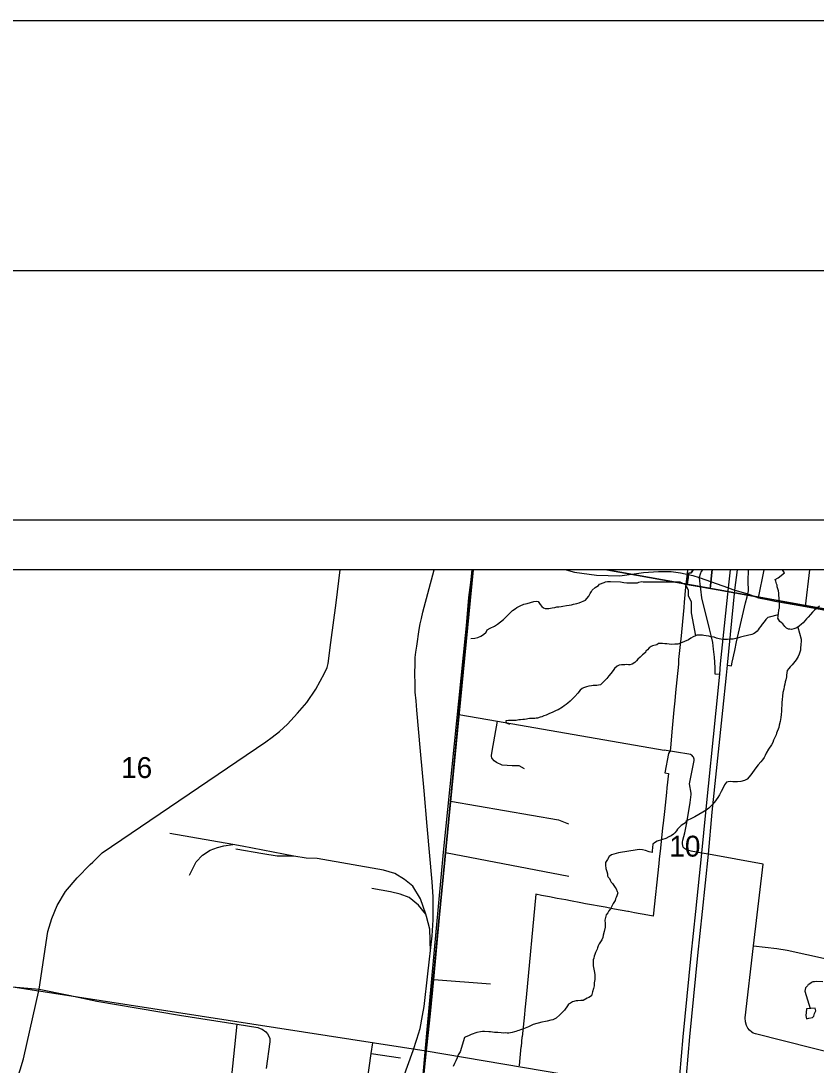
# Model space of a CAD drawing. Extents: x 0 to 34, y -3.9 to 26.2.
# Drawn here: x 6.412 to 8.005, y 19.908 to 22 of the extents above; entities that cross this region are included whole.
import ezdxf

# ---------------------------------------------------------------- set-up
doc = ezdxf.new("R2010")
doc.units = 0
for name, color, linetype in [('GM_X_City_Street', 7, 'Continuous'), ('GM_X_County_Road', 7, 'Continuous'), ('GM_X_Interchange_Ramps', 7, 'Continuous'), ('GM_X_Interstate_Route', 7, 'Continuous'), ('GM_X_Minor_River', 7, 'Continuous'), ('GM_X_Rail_Line', 7, 'Continuous'), ('GM_X_Section', 7, 'Continuous'), ('GM_X_Section_Text', 7, 'Continuous'), ('GM_X_State_Shield', 7, 'Continuous'), ('SH_Border', 7, 'Continuous'), ('SH_Cut_Line', 7, 'Continuous'), ('SH_Data', 7, 'Continuous')]:
    doc.layers.add(name, color=color, linetype=linetype)

msp = doc.modelspace()

# ---------------------------------------------------------------- linework, layer by layer
at = {"layer": 'GM_X_City_Street'}
for p, q in [((7.8891, 20.8439), (7.9002, 20.9)), ((7.9835, 20.8269), (7.9917, 20.9)), ((7.2626, 20.3339), (7.5094, 20.286)), ((7.2392, 20.0793), (7.3526, 20.0709)), ((6.8308, 19.8528), (6.8451, 19.9898)), ((7.1137, 19.9307), (7.1725, 19.9225))]:
    msp.add_line(p, q, dxfattribs=at)
for points in [[(7.289, 20.6105), (7.3664, 20.597), (7.7001, 20.5391)], [(7.4205, 20.5016), (7.41, 20.5071), (7.3959, 20.5074), (7.3759, 20.509), (7.3642, 20.5142), (7.36, 20.5175), (7.3564, 20.5212), (7.3549, 20.5233), (7.3543, 20.5262), (7.3543, 20.5282), (7.3556, 20.5368), (7.3664, 20.597)], [(8.1685, 19.8985), (7.8829, 19.9702), (7.8784, 19.9719), (7.8756, 19.9736), (7.871, 19.9781), (7.8675, 19.982), (7.8651, 19.987), (7.8629, 19.9942), (7.8624, 20.0022), (7.8793, 20.1469), (7.8984, 20.3101), (7.7888, 20.3303), (7.7757, 20.3323), (7.7545, 20.3364), (7.7449, 20.3392), (7.7412, 20.3415), (7.7384, 20.3445), (7.7374, 20.3477), (7.7367, 20.3511), (7.7367, 20.3545), (7.7376, 20.3584), (7.7416, 20.3731), (7.7455, 20.3932), (7.752, 20.4342), (7.754, 20.4497), (7.754, 20.4524), (7.751, 20.4711), (7.7605, 20.5183), (7.7606, 20.5194), (7.7604, 20.5206), (7.7599, 20.5226), (7.7589, 20.5245), (7.7578, 20.5264), (7.7563, 20.5279), (7.755, 20.5289), (7.7533, 20.5298), (7.7496, 20.5311), (7.7001, 20.5391)], [(7.2724, 20.4369), (7.4884, 20.3989), (7.5087, 20.3913)], [(7.8793, 20.1469), (7.9261, 20.1415), (7.9469, 20.138), (8.0251, 20.121), (8.187, 20.0848)], [(7.0598, 19.6739), (7.0846, 19.7416), (7.0857, 19.7471), (7.0871, 19.7545), (7.0914, 19.7791), (7.1047, 19.8692), (7.1137, 19.9307), (7.1169, 19.9525)]]:
    msp.add_lwpolyline(points, dxfattribs=at)
at = {"layer": 'GM_X_County_Road'}
for points in [[(7.0326, 20.7544), (7.0431, 20.8337), (7.0513, 20.9)], [(7.19, 19.616), (7.1965, 19.6759), (7.205, 19.7546), (7.2132, 19.8305), (7.2174, 19.8691), (7.2205, 19.8992), (7.232, 20.0102), (7.2392, 20.0793), (7.2626, 20.3339), (7.2648, 20.3579), (7.2724, 20.4369), (7.289, 20.6105), (7.2945, 20.6675), (7.3089, 20.8445), (7.3161, 20.9)], [(7.5041, 20.9), (7.5206, 20.8956), (7.565, 20.8893), (7.6112, 20.8881), (7.6588, 20.8945), (7.6891, 20.8966), (7.7133, 20.8969)], [(7.7133, 20.8969), (7.7143, 20.8969), (7.7327, 20.8941), (7.7579, 20.8889), (7.7704, 20.8845), (7.8288, 20.8641), (7.8381, 20.861)], [(7.8381, 20.861), (7.8418, 20.8597), (7.8678, 20.8517), (7.8891, 20.8439), (7.9098, 20.84)], [(7.9098, 20.84), (7.9222, 20.8376), (7.9452, 20.8334), (7.9835, 20.8269), (8.0488, 20.8145)], [(6.9025, 20.5558), (6.9155, 20.5646), (6.9302, 20.5765), (6.946, 20.5906), (6.9658, 20.6129), (6.9845, 20.6346), (7.0029, 20.6612), (7.0203, 20.6928), (7.0253, 20.7042), (7.0271, 20.7123), (7.0326, 20.7544)], [(6.5558, 20.3144), (6.5745, 20.333), (6.9025, 20.5558)], [(6.2305, 19.6109), (6.2359, 19.6363), (6.2456, 19.6657), (6.2619, 19.7003), (6.2842, 19.7336), (6.3083, 19.7593), (6.3505, 19.8029), (6.3708, 19.8294), (6.3931, 19.8631), (6.3999, 19.8751), (6.4077, 19.8905), (6.4106, 19.898), (6.417, 19.92), (6.4489, 20.0597), (6.4662, 20.1757), (6.4739, 20.2018), (6.4847, 20.2277), (6.5016, 20.2559), (6.5249, 20.2831), (6.5509, 20.3095), (6.5558, 20.3144)], [(6.3797, 20.0659), (6.4489, 20.0597), (6.5081, 20.0476)], [(6.5081, 20.0476), (6.5644, 20.0361), (6.7293, 20.0075), (6.8451, 19.9898)], [(6.8451, 19.9898), (6.8863, 19.9829), (6.8913, 19.9814), (6.8951, 19.9798), (6.9022, 19.9745), (6.9061, 19.9705), (6.9106, 19.9615), (6.9105, 19.9543), (6.9035, 19.9008)]]:
    msp.add_lwpolyline(points, dxfattribs=at)
at = {"layer": 'GM_X_Interchange_Ramps'}
for points in [[(8.9, 20.9), (7.7963, 20.9), (7.7958, 20.8952), (7.7932, 20.8682), (7.7927, 20.8627), (7.7701, 20.8667), (7.754, 20.8696), (7.7466, 20.8709), (7.7473, 20.8764), (7.7476, 20.8796), (7.749, 20.8913), (7.7492, 20.8934), (7.754, 20.894), (7.7581, 20.9), (7.747, 20.9), (7.7462, 20.893), (7.7462, 20.8929), (7.7449, 20.8812), (7.7444, 20.8769), (7.7437, 20.8714), (7.7432, 20.8655), (7.7404, 20.8354), (7.7394, 20.8249), (7.7334, 20.7614), (7.7329, 20.7564), (7.7291, 20.7206), (7.7287, 20.7111), (7.7256, 20.6796), (7.7231, 20.6543), (7.7215, 20.6374), (7.7197, 20.6194), (7.7161, 20.5828), (7.7129, 20.5432), (7.7124, 20.5374), (7.709, 20.5323), (7.7015, 20.4932), (7.7087, 20.4918), (7.7057, 20.4631), (7.7047, 20.4538), (7.7007, 20.4159), (7.6982, 20.3923), (7.6972, 20.3829), (7.6928, 20.3423), (7.6905, 20.3205), (7.6896, 20.3117), (7.6783, 20.2059), (7.6674, 20.208), (7.641, 20.213), (7.629, 20.2153), (7.6274, 20.2156), (7.6006, 20.2205), (7.5818, 20.2239), (7.5425, 20.2312), (7.5332, 20.233), (7.5125, 20.2369), (7.503, 20.2387), (7.4863, 20.2419), (7.4703, 20.2449), (7.4543, 20.2479), (7.443, 20.25), (7.4237, 20.0431), (7.4214, 20.0186), (7.4205, 20.0092), (7.4162, 19.9645), (7.4155, 19.9642), (7.4136, 19.9447), (7.4135, 19.9442), (7.4106, 19.9147), (7.4098, 19.9061)], [(7.777, 20.9), (7.7746, 20.8965), (7.7725, 20.8914), (7.7704, 20.8845)], [(7.7704, 20.8845), (7.7708, 20.8773), (7.7727, 20.8614), (7.7748, 20.8442), (7.7904, 20.7817), (7.7937, 20.7686), (7.7968, 20.7545), (7.7986, 20.7409), (7.8005, 20.7253), (7.8017, 20.7047), (7.8017, 20.6919), (7.8115, 20.6908)], [(7.8678, 20.8517), (7.869, 20.858), (7.8682, 20.8773), (7.869, 20.9)], [(7.8416, 20.7382), (7.8453, 20.7556), (7.8634, 20.8338), (7.8668, 20.8463), (7.8678, 20.8517)], [(7.8274, 20.7089), (7.8352, 20.708), (7.8367, 20.7153), (7.8416, 20.7382)]]:
    msp.add_lwpolyline(points, dxfattribs=at)
msp.add_lwpolyline([(7.7963, 20.9), (7.7581, 20.9), (7.754, 20.894), (7.7492, 20.8934), (7.749, 20.8913), (7.7476, 20.8796), (7.7473, 20.8764), (7.7466, 20.8709), (7.754, 20.8696), (7.7701, 20.8667), (7.7927, 20.8627), (7.7932, 20.8682), (7.7958, 20.8952)], close=True, dxfattribs=at)
at = {"layer": 'GM_X_Interstate_Route'}
for points in [[(8.9, 20.9), (3.1989, 20.9)], [(7.7314, 19.2555), (7.7327, 19.2893), (7.7318, 19.3378), (7.731, 19.3812), (7.7304, 19.4407), (7.7292, 19.4983), (7.7266, 19.6567), (7.7259, 19.7271), (7.7266, 19.7817), (7.7283, 19.8306), (7.7314, 19.8867), (7.7382, 19.9644), (7.7546, 20.1271), (7.7636, 20.2157), (7.7757, 20.3323), (7.7834, 20.4142), (7.8044, 20.6184), (7.8115, 20.6908), (7.8134, 20.7118), (7.8288, 20.8641), (7.8333, 20.9)], [(7.7421, 19.2233), (7.7429, 19.2303), (7.7447, 19.2555), (7.746, 19.2893), (7.7451, 19.3378), (7.7443, 19.3812), (7.7438, 19.4384), (7.7425, 19.4983), (7.7399, 19.6567), (7.7392, 19.7271), (7.7399, 19.7817), (7.7416, 19.8306), (7.7447, 19.8868), (7.7515, 19.9644), (7.768, 20.1272), (7.7769, 20.2158), (7.7888, 20.3303), (7.7967, 20.4143), (7.8177, 20.6185), (7.8248, 20.6893), (7.8274, 20.7089), (7.8418, 20.8597), (7.8468, 20.9)]]:
    msp.add_lwpolyline(points, dxfattribs=at)
at = {"layer": 'GM_X_Minor_River'}
for p, q in [((7.941, 20.8941), (7.9372, 20.9)), ((8.0028, 20.0218), (7.9852, 20.0203))]:
    msp.add_line(p, q, dxfattribs=at)
for points in [[(8.0111, 20.8273), (8.0016, 20.8193), (7.9976, 20.8153), (7.9932, 20.8105), (7.9887, 20.8053), (7.9852, 20.8017), (7.9823, 20.798), (7.9787, 20.794), (7.9755, 20.791), (7.9708, 20.7874), (7.9657, 20.7838), (7.9599, 20.7818), (7.9556, 20.7808), (7.9518, 20.781), (7.9491, 20.7814), (7.9454, 20.7835), (7.9417, 20.7863), (7.9377, 20.7918), (7.9348, 20.7949), (7.9322, 20.7969), (7.93, 20.7997), (7.9282, 20.8032), (7.9287, 20.8058), (7.9291, 20.8142), (7.93, 20.818), (7.9301, 20.8206), (7.931, 20.8236), (7.9314, 20.8335), (7.9311, 20.8362), (7.9307, 20.8434), (7.9298, 20.8492), (7.9296, 20.8534), (7.929, 20.8583), (7.928, 20.8618), (7.9267, 20.8658), (7.9264, 20.8691), (7.9253, 20.8718), (7.9237, 20.8772), (7.9223, 20.8806), (7.9283, 20.8838), (7.941, 20.8941)], [(7.3129, 20.7627), (7.321, 20.7631), (7.3272, 20.7648), (7.333, 20.7672), (7.3385, 20.7708), (7.3441, 20.7755), (7.3458, 20.78), (7.3516, 20.7832), (7.3606, 20.787), (7.3665, 20.791), (7.3728, 20.796), (7.3787, 20.8007), (7.3847, 20.8066), (7.3915, 20.8135), (7.3967, 20.8187), (7.4018, 20.8219), (7.4053, 20.8244), (7.4116, 20.828), (7.419, 20.8311), (7.4259, 20.8327), (7.4395, 20.8364), (7.4452, 20.8373), (7.4479, 20.8368), (7.4522, 20.8309), (7.4555, 20.8266), (7.4585, 20.8242), (7.4619, 20.8229), (7.4649, 20.8224), (7.4695, 20.8226), (7.476, 20.8239), (7.4811, 20.8248), (7.4853, 20.8258), (7.4895, 20.826), (7.4937, 20.8266), (7.4976, 20.8276), (7.5045, 20.8284), (7.5099, 20.8294), (7.5145, 20.8299), (7.5188, 20.8313), (7.5253, 20.8326), (7.53, 20.8339), (7.5347, 20.836), (7.5381, 20.837), (7.5424, 20.8391), (7.5456, 20.8428), (7.5493, 20.8476), (7.5518, 20.8524), (7.5546, 20.8569), (7.5559, 20.8595), (7.5622, 20.8649), (7.5685, 20.8689), (7.5705, 20.8715), (7.5798, 20.8745), (7.5826, 20.8763), (7.5868, 20.8769), (7.5929, 20.877), (7.6128, 20.8762), (7.6192, 20.8748), (7.6253, 20.8742), (7.6352, 20.8738), (7.6391, 20.8741), (7.6437, 20.8742), (7.6467, 20.8741), (7.6498, 20.8751)], [(7.6498, 20.8751), (7.6553, 20.8768), (7.6582, 20.8762), (7.7315, 20.8762), (7.7428, 20.8705), (7.7484, 20.8593), (7.7484, 20.848), (7.754, 20.8367), (7.754, 20.8142), (7.7628, 20.7679)], [(7.9289, 20.8099), (7.9107, 20.805), (7.9077, 20.8044), (7.9041, 20.8007), (7.9004, 20.7956), (7.8968, 20.7911), (7.8936, 20.7875), (7.8903, 20.783), (7.8883, 20.7801), (7.8863, 20.7775), (7.8823, 20.7738), (7.8792, 20.7717), (7.8757, 20.7707), (7.8587, 20.7668), (7.8533, 20.7655), (7.8471, 20.7631), (7.844, 20.7624), (7.8382, 20.7615), (7.8332, 20.761), (7.8271, 20.7604), (7.8183, 20.7608), (7.8137, 20.7613), (7.8103, 20.7619), (7.805, 20.7632), (7.8001, 20.7649), (7.794, 20.7659), (7.7899, 20.7669), (7.7846, 20.7682), (7.78, 20.7688), (7.777, 20.7693), (7.7735, 20.7694), (7.7701, 20.7692), (7.7659, 20.769), (7.7628, 20.7679), (7.7585, 20.7658), (7.7538, 20.7634), (7.7491, 20.7597), (7.7413, 20.7566), (7.7362, 20.7545), (7.7331, 20.7532), (7.7277, 20.7515), (7.725, 20.7512), (7.7219, 20.7509), (7.7158, 20.7508), (7.7105, 20.751), (7.7055, 20.7516), (7.7017, 20.7521), (7.6968, 20.7527), (7.6918, 20.7525), (7.6891, 20.7522), (7.6856, 20.7501), (7.6771, 20.7478), (7.6739, 20.7464), (7.6704, 20.7439), (7.6672, 20.7398), (7.6636, 20.7373), (7.6628, 20.7347), (7.6572, 20.7299), (7.652, 20.7248), (7.6473, 20.7208), (7.6449, 20.7179), (7.6413, 20.7142), (7.6362, 20.711), (7.6315, 20.7097), (7.6285, 20.7098), (7.625, 20.7103), (7.6216, 20.71), (7.6147, 20.7096), (7.6101, 20.709), (7.6062, 20.7072), (7.601, 20.7025), (7.5978, 20.6981), (7.5933, 20.6925), (7.5897, 20.6877), (7.5853, 20.6822), (7.5805, 20.6778), (7.5725, 20.6698), (7.5687, 20.6688), (7.5656, 20.6682), (7.5618, 20.6683), (7.5579, 20.6681), (7.5545, 20.6678), (7.5495, 20.6673), (7.5444, 20.6656), (7.539, 20.6639), (7.5359, 20.6621), (7.5319, 20.6588), (7.5271, 20.6533), (7.5211, 20.646), (7.5163, 20.6408), (7.5123, 20.6372), (7.5075, 20.6332), (7.504, 20.6303), (7.4997, 20.6274), (7.4965, 20.6249), (7.4879, 20.6199)], [(7.968, 20.7854), (7.9743, 20.7614), (7.9745, 20.7576), (7.9742, 20.75), (7.9736, 20.7436), (7.973, 20.7394), (7.9721, 20.7353), (7.9708, 20.7311), (7.9687, 20.7263), (7.9646, 20.7196), (7.9593, 20.7133), (7.9565, 20.71), (7.9525, 20.7056), (7.9497, 20.7027), (7.9468, 20.6982), (7.9459, 20.6937), (7.9453, 20.6892), (7.9452, 20.6854), (7.9438, 20.6797), (7.9429, 20.6756), (7.9419, 20.6707), (7.9409, 20.6665), (7.9396, 20.6612), (7.9381, 20.6541), (7.9371, 20.6469), (7.9364, 20.6404), (7.9358, 20.6344), (7.9351, 20.6169), (7.9348, 20.6105), (7.9342, 20.6044), (7.9323, 20.5965), (7.9305, 20.589), (7.9299, 20.5844), (7.9252, 20.5728), (7.9243, 20.5694), (7.9189, 20.5586), (7.9176, 20.5541), (7.9151, 20.5496), (7.909, 20.5407), (7.9048, 20.5329), (7.9027, 20.5284), (7.9003, 20.5244), (7.897, 20.5195), (7.8938, 20.5151), (7.8886, 20.5092), (7.8821, 20.5004), (7.8756, 20.4922), (7.8704, 20.4856), (7.8664, 20.4808), (7.8609, 20.478), (7.8539, 20.476), (7.8474, 20.4755), (7.8375, 20.4755), (7.8329, 20.4761), (7.8287, 20.4755), (7.8252, 20.4745), (7.8212, 20.4693), (7.8182, 20.4633), (7.8145, 20.4559), (7.8108, 20.4496), (7.8075, 20.444), (7.8042, 20.4396), (7.801, 20.4347), (7.7962, 20.4292), (7.7926, 20.4252), (7.7898, 20.4226), (7.7843, 20.4187), (7.7776, 20.4144), (7.7619, 20.4051), (7.7537, 20.4012), (7.7479, 20.3984), (7.7439, 20.3959), (7.7427, 20.3933), (7.7395, 20.3912), (7.7341, 20.388), (7.7305, 20.3839), (7.7272, 20.3802), (7.7252, 20.3773), (7.7216, 20.3729), (7.7188, 20.3707), (7.7145, 20.3674), (7.7098, 20.365), (7.7035, 20.3618), (7.6946, 20.3591), (7.6865, 20.3564), (7.681, 20.3532), (7.6778, 20.3503), (7.6768, 20.3438), (7.6765, 20.3374), (7.6764, 20.3336), (7.6703, 20.335), (7.6628, 20.3379), (7.6567, 20.3393), (7.6518, 20.3395), (7.6464, 20.3393), (7.6087, 20.3332), (7.5951, 20.3292), (7.59, 20.326), (7.5867, 20.3197), (7.5826, 20.3137), (7.5828, 20.3084)], [(7.4879, 20.6199), (7.484, 20.6185), (7.477, 20.615), (7.4692, 20.6119), (7.4637, 20.6087), (7.4591, 20.6074), (7.4552, 20.6056), (7.4521, 20.6046), (7.4466, 20.6029), (7.444, 20.6026), (7.4413, 20.602), (7.4386, 20.6021), (7.4332, 20.6019), (7.4306, 20.602), (7.4275, 20.6018), (7.4248, 20.6011), (7.4205, 20.6005), (7.4171, 20.6003), (7.4125, 20.5997), (7.409, 20.5995), (7.4036, 20.5985), (7.3998, 20.5983), (7.396, 20.5985), (7.3925, 20.5982), (7.3883, 20.598), (7.3833, 20.5974), (7.3839, 20.5936), (7.3907, 20.5911)], [(7.5828, 20.3084), (7.5837, 20.3019), (7.5853, 20.2954), (7.5867, 20.2911), (7.5869, 20.2873), (7.5883, 20.2842), (7.5905, 20.2815), (7.5919, 20.2784), (7.5944, 20.2745), (7.5966, 20.2717), (7.5995, 20.2678), (7.602, 20.2639), (7.6038, 20.2608), (7.6062, 20.2557), (7.6073, 20.2527), (7.6055, 20.247), (7.6042, 20.2433), (7.6029, 20.2407), (7.6024, 20.2376), (7.5984, 20.2317), (7.595, 20.225), (7.5926, 20.2209), (7.5897, 20.2172), (7.5873, 20.2131), (7.5844, 20.2091), (7.5835, 20.206), (7.5817, 20.1981), (7.5822, 20.1916), (7.5819, 20.1844), (7.5804, 20.1757), (7.5778, 20.1679), (7.5772, 20.1637), (7.5751, 20.1585), (7.5702, 20.1507), (7.5681, 20.1469), (7.5668, 20.1428), (7.5659, 20.1398), (7.563, 20.1335), (7.5613, 20.1293), (7.56, 20.1263), (7.5594, 20.1222), (7.5581, 20.1184), (7.5579, 20.1124), (7.5584, 20.1066), (7.5597, 20.1001), (7.5605, 20.0936), (7.5611, 20.0886), (7.5614, 20.086), (7.5611, 20.0791), (7.56, 20.0723), (7.5598, 20.0666), (7.5588, 20.0613), (7.557, 20.0546), (7.5557, 20.0493), (7.5544, 20.0463), (7.5493, 20.0435), (7.5462, 20.0417), (7.538, 20.0375), (7.5333, 20.0369), (7.5276, 20.0367), (7.5238, 20.0365), (7.5164, 20.0345), (7.5125, 20.0316), (7.509, 20.0299), (7.5065, 20.0265), (7.5005, 20.018), (7.4916, 20.0085), (7.4837, 20.0016), (7.4802, 19.9998), (7.4771, 19.9988), (7.4732, 19.9978), (7.4659, 19.9958), (7.4628, 19.9952), (7.4555, 19.9936), (7.4381, 19.9889), (7.4283, 19.9844), (7.4186, 19.9802), (7.4128, 19.9782), (7.4093, 19.9772), (7.4066, 19.9765), (7.4031, 19.9751), (7.4004, 19.9745), (7.3961, 19.9731), (7.3926, 19.9721), (7.3892, 19.9715), (7.3861, 19.9716), (7.3827, 19.9721), (7.3789, 19.9719), (7.3735, 19.9725), (7.3671, 19.9731), (7.3606, 19.9734), (7.3526, 19.9745), (7.3492, 19.9746), (7.3404, 19.9753), (7.3366, 19.9751), (7.3327, 19.9745), (7.3254, 19.9729), (7.3138, 19.9688), (7.3083, 19.9664), (7.3029, 19.9643), (7.3001, 19.9629)], [(8.0178, 20.0746), (8.0044, 20.0752), (8.001, 20.0749), (7.9983, 20.0743), (7.9952, 20.0736), (7.9912, 20.07), (7.9885, 20.069), (7.9872, 20.0663), (7.9836, 20.0623), (7.9823, 20.0556), (7.9929, 20.021)], [(7.9852, 20.0203), (7.9844, 20.0131), (7.9839, 20.0074), (7.9853, 20.0005), (7.9902, 20.0016), (7.9971, 20.0033), (7.9998, 20.0059), (8.0011, 20.0112), (8.0042, 20.0165), (8.0028, 20.0218)], [(7.3001, 19.9629), (7.2916, 19.9344), (7.2879, 19.9284), (7.2854, 19.9221), (7.2833, 19.9161), (7.2804, 19.9109), (7.2779, 19.9053)]]:
    msp.add_lwpolyline(points, dxfattribs=at)
at = {"layer": 'GM_X_Rail_Line'}
msp.add_line((6.8362, 20.3497), (6.7104, 20.3716), dxfattribs=at)
for points in [[(7.1178, 19.7152), (7.1979, 19.9367), (7.2051, 19.9594), (7.2113, 19.9811), (7.2164, 20.0069), (7.2195, 20.025), (7.2271, 20.0909), (7.2358, 20.167), (7.2375, 20.1986), (7.2379, 20.2218), (7.2377, 20.2446), (7.2356, 20.275), (7.2257, 20.3866), (7.2194, 20.4574), (7.2121, 20.5371), (7.2052, 20.6188), (7.2035, 20.6379), (7.2019, 20.6552), (7.2014, 20.6715), (7.2011, 20.6917), (7.2016, 20.7124), (7.2019, 20.7245), (7.2029, 20.7354), (7.2048, 20.7473), (7.2097, 20.7805), (7.2118, 20.7918), (7.2145, 20.8025), (7.2171, 20.8156), (7.2397, 20.9)], [(7.204, 19.7377), (7.2256, 19.9791), (7.2586, 20.3343), (7.3157, 20.9)], [(6.7499, 20.2882), (6.7632, 20.3153), (6.7755, 20.3282), (6.7908, 20.3385), (6.8056, 20.3439), (6.8184, 20.3469), (6.8362, 20.3497)], [(6.9585, 20.3262), (6.8549, 20.3464), (6.8362, 20.3497)], [(6.9585, 20.3262), (6.925, 20.3267), (6.8968, 20.3311), (6.8426, 20.3405)], [(7.2228, 20.2104), (7.2125, 20.2409), (7.1972, 20.266), (7.1804, 20.2798), (7.1607, 20.2917), (7.1385, 20.2986), (7.0053, 20.3217), (6.9832, 20.3222), (6.9585, 20.3262)], [(7.2228, 20.2104), (7.2085, 20.228), (7.1893, 20.2438), (7.1716, 20.2502), (7.1523, 20.2552), (7.1148, 20.2616)], [(7.2322, 20.1355), (7.2312, 20.1802), (7.2243, 20.2058), (7.2228, 20.2104)]]:
    msp.add_lwpolyline(points, dxfattribs=at)
at = {"layer": 'GM_X_Section'}
for points in [[(6.1758, 20.0989), (7.2234, 19.9362), (7.1209, 18.9374), (6.0727, 19.072)], [(7.2234, 19.9362), (8.165, 19.7765), (8.0693, 18.7631), (7.1209, 18.9374)]]:
    msp.add_lwpolyline(points, close=True, dxfattribs=at)
at = {"layer": 'GM_X_State_Shield'}
for points in [[(7.3179, 20.9), (6.2505, 20.9), (6.1758, 20.0989), (7.2234, 19.9362)], [(7.5857, 20.9), (7.3179, 20.9), (7.2234, 19.9362), (8.165, 19.7765), (8.262, 20.7786)], [(8.2736, 20.9), (7.5857, 20.9), (8.262, 20.7786)]]:
    msp.add_lwpolyline(points, close=True, dxfattribs=at)
at = {"layer": 'SH_Border'}
msp.add_lwpolyline([(1.5, 21.5), (33.5, 21.5), (33.5, 0.5), (1.5, 0.5)], close=True, dxfattribs=at)
at = {"layer": 'SH_Cut_Line'}
msp.add_lwpolyline([(0, 0), (34, 0), (34, 22), (0, 22)], close=True, dxfattribs=at)
at = {"layer": 'SH_Data'}
msp.add_line((2, 21), (9, 21), dxfattribs=at)

# ---------------------------------------------------------------- texts
at = {"layer": 'GM_X_Section_Text'}
for s, p in [('16', (6.6127, 20.483)), ('10', (7.7106, 20.3255))]:
    msp.add_text(s, height=0.04186, rotation=0, dxfattribs=at).set_placement(p)

doc.saveas('drawing.dxf')
